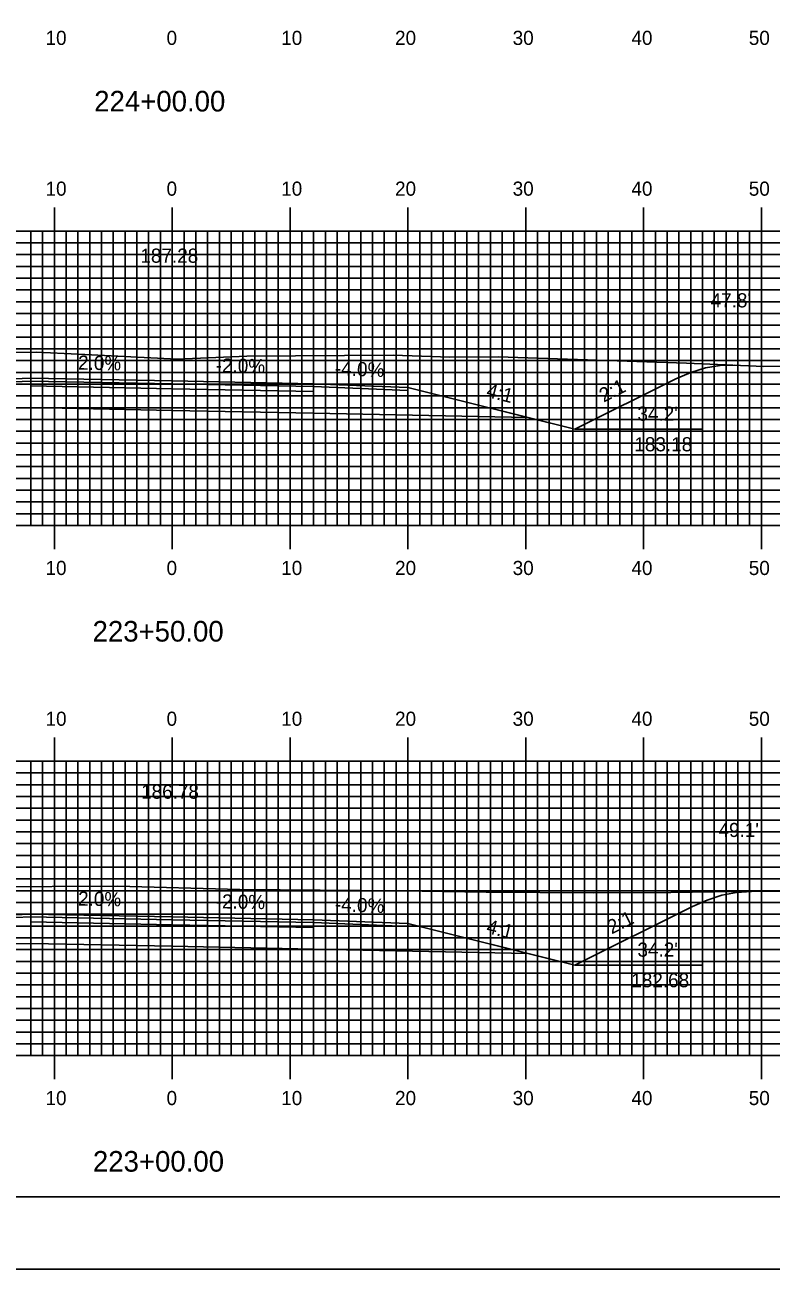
# Model space of a CAD drawing. Extents: x 1797994 to 1798337, y 442591 to 442811.
# Drawn here: x 1798147.5 to 1798210.8, y 442590.5 to 442696.2 of the extents above; entities that cross this region are included whole.
import ezdxf

# ---------------------------------------------------------------- set-up
doc = ezdxf.new("R2010")
doc.units = 0
for name, color, linetype in [('ANNOTATION', 7, 'Continuous'), ('BORDER', 7, 'Continuous'), ('D_Roadway_Centerline', 7, 'Continuous'), ('D_Roadway_Centerline_Text', 7, 'Continuous'), ('D_Roadway_Edge_Shoulder', 7, 'Continuous'), ('D_Roadway_Edge_TW', 7, 'Continuous'), ('D_Roadway_Pavement', 7, 'Continuous'), ('D_Roadway_SlopeLines', 7, 'Continuous'), ('D_Roadway_SubGrade', 7, 'Continuous'), ('D_Text_Standard', 7, 'Continuous'), ('H_V ANNOTATION', 7, 'Continuous'), ('MAJOR', 7, 'Continuous'), ('MINOR', 7, 'Continuous'), ('PDRAIN', 7, 'Continuous'), ('PLOT BOUNDARY', 7, 'Continuous'), ('S_Roadway_Centerline', 7, 'Continuous')]:
    doc.layers.add(name, color=color, linetype=linetype)

msp = doc.modelspace()

# ---------------------------------------------------------------- linework, layer by layer
at = {"layer": 'BORDER'}
msp.add_lwpolyline([(1798010.36, 442596.67), (1798330.36, 442596.67), (1798330.36, 442806.67), (1798010.36, 442806.67)], close=True, dxfattribs=at)
at = {"layer": 'D_Roadway_Centerline'}
for points in [[(1798111.32, 442668.33), (1798112.57, 442668.24), (1798113.82, 442668), (1798115.07, 442667.61), (1798116.32, 442667.06), (1798125.78, 442662.33), (1798129.78, 442663.33), (1798139.96, 442665.87), (1798147.96, 442666.19), (1798159.96, 442665.95), (1798171.96, 442665.71), (1798179.96, 442665.39), (1798190.13, 442662.85), (1798194.13, 442661.85), (1798202.71, 442666.13), (1798203.96, 442666.67), (1798205.21, 442667.05), (1798206.46, 442667.25), (1798207.71, 442667.28)], [(1798109.84, 442623.56), (1798111.09, 442623.48), (1798112.34, 442623.24), (1798113.59, 442622.85), (1798114.84, 442622.3), (1798125.78, 442616.83), (1798129.78, 442617.83), (1798139.96, 442620.37), (1798147.96, 442620.69), (1798159.96, 442620.45), (1798171.96, 442620.21), (1798179.96, 442619.89), (1798190.13, 442617.35), (1798194.13, 442616.35), (1798204.11, 442621.33), (1798205.36, 442621.88), (1798206.61, 442622.28), (1798207.86, 442622.52), (1798209.11, 442622.61)]]:
    msp.add_lwpolyline(points, dxfattribs=at)
at = {"layer": 'D_Roadway_Edge_Shoulder'}
for points in [[(1798147.96, 442666.19), (1798139.96, 442665.87), (1798139.96, 442665.62), (1798147.96, 442665.94)], [(1798171.96, 442665.71), (1798179.96, 442665.39), (1798179.96, 442665.14), (1798171.96, 442665.46)], [(1798147.96, 442620.69), (1798139.96, 442620.37), (1798139.96, 442620.12), (1798147.96, 442620.44)], [(1798171.96, 442620.21), (1798179.96, 442619.89), (1798179.96, 442619.64), (1798171.96, 442619.96)]]:
    msp.add_lwpolyline(points, close=True, dxfattribs=at)
at = {"layer": 'D_Roadway_Edge_TW'}
for points in [[(1798147.96, 442665.94), (1798147.96, 442666.19), (1798159.96, 442665.95), (1798171.96, 442665.71), (1798171.96, 442665.46), (1798159.96, 442665.7)], [(1798147.96, 442620.44), (1798147.96, 442620.69), (1798159.96, 442620.45), (1798171.96, 442620.21), (1798171.96, 442619.96), (1798159.96, 442620.2)]]:
    msp.add_lwpolyline(points, close=True, dxfattribs=at)
at = {"layer": 'D_Roadway_Pavement'}
for points in [[(1798147.96, 442665.52), (1798147.96, 442665.94), (1798159.96, 442665.7), (1798171.96, 442665.46), (1798171.96, 442665.04), (1798159.96, 442665.28)], [(1798147.96, 442620.02), (1798147.96, 442620.44), (1798159.96, 442620.2), (1798171.96, 442619.96), (1798171.96, 442619.54), (1798159.96, 442619.78)]]:
    msp.add_lwpolyline(points, close=True, dxfattribs=at)
at = {"layer": 'D_Roadway_SlopeLines'}
for points in [[(1798194.13, 442661.85), (1798202.71, 442666.13), (1798203.96, 442666.67), (1798205.21, 442667.05), (1798206.46, 442667.25), (1798207.71, 442667.28)], [(1798179.96, 442665.39), (1798194.13, 442661.85)], [(1798194.13, 442616.35), (1798204.11, 442621.33), (1798205.36, 442621.88), (1798206.61, 442622.28), (1798207.86, 442622.52), (1798209.11, 442622.61)], [(1798179.96, 442619.89), (1798194.13, 442616.35)]]:
    msp.add_lwpolyline(points, dxfattribs=at)
at = {"layer": 'D_Roadway_SubGrade'}
for points in [[(1798147.96, 442663.69), (1798129.78, 442663.33), (1798139.96, 442665.87), (1798139.96, 442665.62), (1798147.96, 442665.94), (1798159.96, 442665.7), (1798171.96, 442665.46), (1798179.96, 442665.14), (1798179.96, 442665.39), (1798190.13, 442662.85), (1798171.96, 442663.21), (1798159.96, 442663.45)], [(1798147.96, 442618.19), (1798129.78, 442617.83), (1798139.96, 442620.37), (1798139.96, 442620.12), (1798147.96, 442620.44), (1798159.96, 442620.2), (1798171.96, 442619.96), (1798179.96, 442619.64), (1798179.96, 442619.89), (1798190.13, 442617.35), (1798171.96, 442617.71), (1798159.96, 442617.95)]]:
    msp.add_lwpolyline(points, close=True, dxfattribs=at)
at = {"layer": 'MAJOR'}
for p, q in [((1798149.96, 442680.67), (1798149.96, 442678.67)), ((1798159.96, 442680.67), (1798159.96, 442678.67)), ((1798169.96, 442680.67), (1798169.96, 442678.67)), ((1798179.96, 442680.67), (1798179.96, 442678.67)), ((1798189.96, 442680.67), (1798189.96, 442678.67)), ((1798199.96, 442680.67), (1798199.96, 442678.67)), ((1798209.96, 442680.67), (1798209.96, 442678.67)), ((1798019.96, 442678.67), (1798299.96, 442678.67)), ((1798019.96, 442678.67), (1798299.96, 442678.67)), ((1798149.96, 442653.67), (1798149.96, 442678.67)), ((1798159.96, 442653.67), (1798159.96, 442678.67)), ((1798169.96, 442653.67), (1798169.96, 442678.67)), ((1798179.96, 442653.67), (1798179.96, 442678.67)), ((1798189.96, 442653.67), (1798189.96, 442678.67)), ((1798199.96, 442653.67), (1798199.96, 442678.67)), ((1798209.96, 442653.67), (1798209.96, 442678.67)), ((1798019.96, 442673.67), (1798299.96, 442673.67)), ((1798019.96, 442668.67), (1798299.96, 442668.67)), ((1798019.96, 442663.67), (1798299.96, 442663.67)), ((1798019.96, 442658.67), (1798299.96, 442658.67)), ((1798019.96, 442653.67), (1798299.96, 442653.67)), ((1798019.96, 442653.67), (1798299.96, 442653.67)), ((1798149.96, 442651.66), (1798149.96, 442653.67)), ((1798159.96, 442651.66), (1798159.96, 442653.67)), ((1798169.96, 442651.66), (1798169.96, 442653.67)), ((1798179.96, 442651.66), (1798179.96, 442653.67)), ((1798189.96, 442651.66), (1798189.96, 442653.67)), ((1798199.96, 442651.66), (1798199.96, 442653.67)), ((1798209.96, 442651.66), (1798209.96, 442653.67)), ((1798149.96, 442635.67), (1798149.96, 442633.67)), ((1798159.96, 442635.67), (1798159.96, 442633.67)), ((1798169.96, 442635.67), (1798169.96, 442633.67)), ((1798179.96, 442635.67), (1798179.96, 442633.67)), ((1798189.96, 442635.67), (1798189.96, 442633.67)), ((1798199.96, 442635.67), (1798199.96, 442633.67)), ((1798209.96, 442635.67), (1798209.96, 442633.67)), ((1798019.96, 442633.67), (1798299.96, 442633.67)), ((1798019.96, 442633.67), (1798299.96, 442633.67)), ((1798149.96, 442608.67), (1798149.96, 442633.67)), ((1798159.96, 442608.67), (1798159.96, 442633.67)), ((1798169.96, 442608.67), (1798169.96, 442633.67)), ((1798179.96, 442608.67), (1798179.96, 442633.67)), ((1798189.96, 442608.67), (1798189.96, 442633.67)), ((1798199.96, 442608.67), (1798199.96, 442633.67)), ((1798209.96, 442608.67), (1798209.96, 442633.67)), ((1798019.96, 442628.67), (1798299.96, 442628.67)), ((1798019.96, 442623.67), (1798299.96, 442623.67)), ((1798019.96, 442618.67), (1798299.96, 442618.67)), ((1798019.96, 442613.67), (1798299.96, 442613.67)), ((1798019.96, 442608.67), (1798299.96, 442608.67)), ((1798019.96, 442608.67), (1798299.96, 442608.67)), ((1798149.96, 442606.66), (1798149.96, 442608.67)), ((1798159.96, 442606.66), (1798159.96, 442608.67)), ((1798169.96, 442606.66), (1798169.96, 442608.67)), ((1798179.96, 442606.66), (1798179.96, 442608.67)), ((1798189.96, 442606.66), (1798189.96, 442608.67)), ((1798199.96, 442606.66), (1798199.96, 442608.67)), ((1798209.96, 442606.66), (1798209.96, 442608.67))]:
    msp.add_line(p, q, dxfattribs=at)
at = {"layer": 'MINOR'}
for p, q in [((1798147.96, 442653.67), (1798147.96, 442678.67)), ((1798148.96, 442653.67), (1798148.96, 442678.67)), ((1798150.96, 442653.67), (1798150.96, 442678.67)), ((1798151.96, 442653.67), (1798151.96, 442678.67)), ((1798152.96, 442653.67), (1798152.96, 442678.67)), ((1798153.96, 442653.67), (1798153.96, 442678.67)), ((1798154.96, 442653.67), (1798154.96, 442678.67)), ((1798155.96, 442653.67), (1798155.96, 442678.67)), ((1798156.96, 442653.67), (1798156.96, 442678.67)), ((1798157.96, 442653.67), (1798157.96, 442678.67)), ((1798158.96, 442653.67), (1798158.96, 442678.67)), ((1798160.96, 442653.67), (1798160.96, 442678.67)), ((1798161.96, 442653.67), (1798161.96, 442678.67)), ((1798162.96, 442653.67), (1798162.96, 442678.67)), ((1798163.96, 442653.67), (1798163.96, 442678.67)), ((1798164.96, 442653.67), (1798164.96, 442678.67)), ((1798165.96, 442653.67), (1798165.96, 442678.67)), ((1798166.96, 442653.67), (1798166.96, 442678.67)), ((1798167.96, 442653.67), (1798167.96, 442678.67)), ((1798168.96, 442653.67), (1798168.96, 442678.67)), ((1798170.96, 442653.67), (1798170.96, 442678.67)), ((1798171.96, 442653.67), (1798171.96, 442678.67)), ((1798172.96, 442653.67), (1798172.96, 442678.67)), ((1798173.96, 442653.67), (1798173.96, 442678.67)), ((1798174.96, 442653.67), (1798174.96, 442678.67)), ((1798175.96, 442653.67), (1798175.96, 442678.67)), ((1798176.96, 442653.67), (1798176.96, 442678.67)), ((1798177.96, 442653.67), (1798177.96, 442678.67)), ((1798178.96, 442653.67), (1798178.96, 442678.67)), ((1798180.96, 442653.67), (1798180.96, 442678.67)), ((1798181.96, 442653.67), (1798181.96, 442678.67)), ((1798182.96, 442653.67), (1798182.96, 442678.67)), ((1798183.96, 442653.67), (1798183.96, 442678.67)), ((1798184.96, 442653.67), (1798184.96, 442678.67)), ((1798185.96, 442653.67), (1798185.96, 442678.67)), ((1798186.96, 442653.67), (1798186.96, 442678.67)), ((1798187.96, 442653.67), (1798187.96, 442678.67)), ((1798188.96, 442653.67), (1798188.96, 442678.67)), ((1798190.96, 442653.67), (1798190.96, 442678.67)), ((1798191.96, 442653.67), (1798191.96, 442678.67)), ((1798192.96, 442653.67), (1798192.96, 442678.67)), ((1798193.96, 442653.67), (1798193.96, 442678.67)), ((1798194.96, 442653.67), (1798194.96, 442678.67)), ((1798195.96, 442653.67), (1798195.96, 442678.67)), ((1798196.96, 442653.67), (1798196.96, 442678.67)), ((1798197.96, 442653.67), (1798197.96, 442678.67)), ((1798198.96, 442653.67), (1798198.96, 442678.67)), ((1798200.96, 442653.67), (1798200.96, 442678.67)), ((1798201.96, 442653.67), (1798201.96, 442678.67)), ((1798202.96, 442653.67), (1798202.96, 442678.67)), ((1798203.96, 442653.67), (1798203.96, 442678.67)), ((1798204.96, 442653.67), (1798204.96, 442678.67)), ((1798205.96, 442653.67), (1798205.96, 442678.67)), ((1798206.96, 442653.67), (1798206.96, 442678.67)), ((1798207.96, 442653.67), (1798207.96, 442678.67)), ((1798208.96, 442653.67), (1798208.96, 442678.67)), ((1798019.96, 442677.67), (1798299.96, 442677.67)), ((1798019.96, 442676.67), (1798299.96, 442676.67)), ((1798019.96, 442675.67), (1798299.96, 442675.67)), ((1798019.96, 442674.67), (1798299.96, 442674.67)), ((1798019.96, 442672.67), (1798299.96, 442672.67)), ((1798019.96, 442671.67), (1798299.96, 442671.67)), ((1798019.96, 442670.67), (1798299.96, 442670.67)), ((1798019.96, 442669.67), (1798299.96, 442669.67)), ((1798019.96, 442667.67), (1798299.96, 442667.67)), ((1798019.96, 442666.67), (1798299.96, 442666.67)), ((1798019.96, 442665.67), (1798299.96, 442665.67)), ((1798019.96, 442664.67), (1798299.96, 442664.67)), ((1798019.96, 442662.67), (1798299.96, 442662.67)), ((1798019.96, 442661.67), (1798299.96, 442661.67)), ((1798019.96, 442660.67), (1798299.96, 442660.67)), ((1798019.96, 442659.67), (1798299.96, 442659.67)), ((1798019.96, 442657.67), (1798299.96, 442657.67)), ((1798019.96, 442656.67), (1798299.96, 442656.67)), ((1798019.96, 442655.67), (1798299.96, 442655.67)), ((1798019.96, 442654.67), (1798299.96, 442654.67)), ((1798147.96, 442608.67), (1798147.96, 442633.67)), ((1798148.96, 442608.67), (1798148.96, 442633.67)), ((1798150.96, 442608.67), (1798150.96, 442633.67)), ((1798151.96, 442608.67), (1798151.96, 442633.67)), ((1798152.96, 442608.67), (1798152.96, 442633.67)), ((1798153.96, 442608.67), (1798153.96, 442633.67)), ((1798154.96, 442608.67), (1798154.96, 442633.67)), ((1798155.96, 442608.67), (1798155.96, 442633.67)), ((1798156.96, 442608.67), (1798156.96, 442633.67)), ((1798157.96, 442608.67), (1798157.96, 442633.67)), ((1798158.96, 442608.67), (1798158.96, 442633.67)), ((1798160.96, 442608.67), (1798160.96, 442633.67)), ((1798161.96, 442608.67), (1798161.96, 442633.67)), ((1798162.96, 442608.67), (1798162.96, 442633.67)), ((1798163.96, 442608.67), (1798163.96, 442633.67)), ((1798164.96, 442608.67), (1798164.96, 442633.67)), ((1798165.96, 442608.67), (1798165.96, 442633.67)), ((1798166.96, 442608.67), (1798166.96, 442633.67)), ((1798167.96, 442608.67), (1798167.96, 442633.67)), ((1798168.96, 442608.67), (1798168.96, 442633.67)), ((1798170.96, 442608.67), (1798170.96, 442633.67)), ((1798171.96, 442608.67), (1798171.96, 442633.67)), ((1798172.96, 442608.67), (1798172.96, 442633.67)), ((1798173.96, 442608.67), (1798173.96, 442633.67)), ((1798174.96, 442608.67), (1798174.96, 442633.67)), ((1798175.96, 442608.67), (1798175.96, 442633.67)), ((1798176.96, 442608.67), (1798176.96, 442633.67)), ((1798177.96, 442608.67), (1798177.96, 442633.67)), ((1798178.96, 442608.67), (1798178.96, 442633.67)), ((1798180.96, 442608.67), (1798180.96, 442633.67)), ((1798181.96, 442608.67), (1798181.96, 442633.67)), ((1798182.96, 442608.67), (1798182.96, 442633.67)), ((1798183.96, 442608.67), (1798183.96, 442633.67)), ((1798184.96, 442608.67), (1798184.96, 442633.67)), ((1798185.96, 442608.67), (1798185.96, 442633.67)), ((1798186.96, 442608.67), (1798186.96, 442633.67)), ((1798187.96, 442608.67), (1798187.96, 442633.67)), ((1798188.96, 442608.67), (1798188.96, 442633.67)), ((1798190.96, 442608.67), (1798190.96, 442633.67)), ((1798191.96, 442608.67), (1798191.96, 442633.67)), ((1798192.96, 442608.67), (1798192.96, 442633.67)), ((1798193.96, 442608.67), (1798193.96, 442633.67)), ((1798194.96, 442608.67), (1798194.96, 442633.67)), ((1798195.96, 442608.67), (1798195.96, 442633.67)), ((1798196.96, 442608.67), (1798196.96, 442633.67)), ((1798197.96, 442608.67), (1798197.96, 442633.67)), ((1798198.96, 442608.67), (1798198.96, 442633.67)), ((1798200.96, 442608.67), (1798200.96, 442633.67)), ((1798201.96, 442608.67), (1798201.96, 442633.67)), ((1798202.96, 442608.67), (1798202.96, 442633.67)), ((1798203.96, 442608.67), (1798203.96, 442633.67)), ((1798204.96, 442608.67), (1798204.96, 442633.67)), ((1798205.96, 442608.67), (1798205.96, 442633.67)), ((1798206.96, 442608.67), (1798206.96, 442633.67)), ((1798207.96, 442608.67), (1798207.96, 442633.67)), ((1798208.96, 442608.67), (1798208.96, 442633.67)), ((1798019.96, 442632.67), (1798299.96, 442632.67)), ((1798019.96, 442631.67), (1798299.96, 442631.67)), ((1798019.96, 442630.67), (1798299.96, 442630.67)), ((1798019.96, 442629.67), (1798299.96, 442629.67)), ((1798019.96, 442627.67), (1798299.96, 442627.67)), ((1798019.96, 442626.67), (1798299.96, 442626.67)), ((1798019.96, 442625.67), (1798299.96, 442625.67)), ((1798019.96, 442624.67), (1798299.96, 442624.67)), ((1798019.96, 442622.67), (1798299.96, 442622.67)), ((1798019.96, 442621.67), (1798299.96, 442621.67)), ((1798019.96, 442620.67), (1798299.96, 442620.67)), ((1798019.96, 442619.67), (1798299.96, 442619.67)), ((1798019.96, 442617.67), (1798299.96, 442617.67)), ((1798019.96, 442616.67), (1798299.96, 442616.67)), ((1798019.96, 442615.67), (1798299.96, 442615.67)), ((1798019.96, 442614.67), (1798299.96, 442614.67)), ((1798019.96, 442612.67), (1798299.96, 442612.67)), ((1798019.96, 442611.67), (1798299.96, 442611.67)), ((1798019.96, 442610.67), (1798299.96, 442610.67)), ((1798019.96, 442609.67), (1798299.96, 442609.67))]:
    msp.add_line(p, q, dxfattribs=at)
at = {"layer": 'PDRAIN'}
for p, q in [((1798194.13, 442661.85), (1798204.9, 442661.85)), ((1798194.13, 442616.35), (1798204.9, 442616.35))]:
    msp.add_line(p, q, dxfattribs=at)
at = {"layer": 'PLOT BOUNDARY'}
msp.add_lwpolyline([(1797994.17, 442590.55), (1798334.17, 442590.55), (1798334.17, 442810.55), (1797994.17, 442810.55)], close=True, dxfattribs=at)
at = {"layer": 'S_Roadway_Centerline'}
for points in [[(1798102.25, 442668.41), (1798102.51, 442668.41), (1798105.32, 442668.38), (1798123.11, 442668.23), (1798124.43, 442668.16), (1798126.54, 442668.15), (1798137.46, 442668.24), (1798145.98, 442668.37), (1798148.44, 442668.4), (1798151.99, 442668.21), (1798160.37, 442667.79), (1798166.3, 442668.04), (1798178.7, 442668.14), (1798183.51, 442667.97), (1798187.61, 442668), (1798203.6, 442667.45), (1798210.16, 442667.18), (1798218.97, 442667.3)], [(1798019.96, 442624.18), (1798026.96, 442624.23), (1798036.73, 442624.33), (1798039.99, 442624.27), (1798059.51, 442623.72), (1798061.88, 442623.71), (1798065.3, 442623.74), (1798080.87, 442623.7), (1798092, 442623.71), (1798102.39, 442623.6), (1798118.19, 442623.52), (1798120.17, 442623.54), (1798121.59, 442623.48), (1798143.17, 442622.99), (1798143.68, 442622.99), (1798144.17, 442623), (1798155.33, 442623.07), (1798165.69, 442622.78), (1798179.35, 442622.67), (1798186.61, 442622.56), (1798195.7, 442622.49), (1798202.28, 442622.51), (1798207.69, 442622.6), (1798213.43, 442622.63)]]:
    msp.add_lwpolyline(points, dxfattribs=at)

# ---------------------------------------------------------------- texts
at = {"layer": 'ANNOTATION'}
for s, rotation, p in [('2.0%', 358.8542, (1798151.96, 442666.91)), ('-2.0%', 358.8542, (1798163.64, 442666.68)), ('-4.0%', 357.7094, (1798173.75, 442666.44)), ('2:1', 26.5651, (1798196.57, 442664.1)), ('4:1', 345.9638, (1798186.55, 442664.6)), ('2.0%', 358.8542, (1798151.96, 442621.41)), ('-2.0%', 358.8542, (1798163.64, 442621.18)), ('-4.0%', 357.7094, (1798173.75, 442620.94)), ('2:1', 26.5651, (1798197.26, 442618.95)), ('4:1', 345.9638, (1798186.55, 442619.1))]:
    msp.add_text(s, height=1.2, rotation=rotation, dxfattribs=at).set_placement(p)
for s, p in [("34.2'", (1798199.44, 442662.57)), ('183.18', (1798199.18, 442659.97)), ("34.2'", (1798199.44, 442617.07)), ('182.68', (1798198.92, 442614.47))]:
    msp.add_text(s, height=1.2, dxfattribs=at).set_placement(p)
at = {"layer": 'D_Roadway_Centerline'}
for s, p in [('C', (1798159.95, 442665.95)), ('L', (1798159.96, 442665.94)), ('C', (1798159.95, 442620.45)), ('L', (1798159.96, 442620.44))]:
    msp.add_text(s, height=0.0146, dxfattribs=at).set_placement(p)
at = {"layer": 'D_Roadway_Centerline_Text'}
for s, p in [('187.28', (1798157.26, 442675.98)), ('186.78', (1798157.32, 442630.48))]:
    msp.add_text(s, height=1.2, dxfattribs=at).set_placement(p)
at = {"layer": 'D_Text_Standard'}
for s, p in [("47.8'", (1798205.65, 442672.19)), ("49.1'", (1798206.32, 442627.23))]:
    msp.add_text(s, height=1.2, dxfattribs=at).set_placement(p)
at = {"layer": 'H_V ANNOTATION'}
for s, height, p in [('10', 1.2, (1798149.21, 442694.47)), ('0', 1.2, (1798159.48, 442694.47)), ('10', 1.2, (1798169.21, 442694.47)), ('20', 1.2, (1798178.87, 442694.47)), ('30', 1.2, (1798188.85, 442694.47)), ('40', 1.2, (1798198.93, 442694.47)), ('50', 1.2, (1798208.89, 442694.47)), ('224+00.00', 1.75, (1798153.34, 442688.82)), ('10', 1.2, (1798149.21, 442681.67)), ('0', 1.2, (1798159.48, 442681.67)), ('10', 1.2, (1798169.21, 442681.67)), ('20', 1.2, (1798178.87, 442681.67)), ('30', 1.2, (1798188.85, 442681.67)), ('40', 1.2, (1798198.93, 442681.67)), ('50', 1.2, (1798208.89, 442681.67)), ('10', 1.2, (1798149.21, 442649.47)), ('0', 1.2, (1798159.48, 442649.47)), ('10', 1.2, (1798169.21, 442649.47)), ('20', 1.2, (1798178.87, 442649.47)), ('30', 1.2, (1798188.85, 442649.47)), ('40', 1.2, (1798198.93, 442649.47)), ('50', 1.2, (1798208.89, 442649.47)), ('223+50.00', 1.75, (1798153.2, 442643.82)), ('10', 1.2, (1798149.21, 442636.67)), ('0', 1.2, (1798159.48, 442636.67)), ('10', 1.2, (1798169.21, 442636.67)), ('20', 1.2, (1798178.87, 442636.67)), ('30', 1.2, (1798188.85, 442636.67)), ('40', 1.2, (1798198.93, 442636.67)), ('50', 1.2, (1798208.89, 442636.67)), ('10', 1.2, (1798149.21, 442604.47)), ('0', 1.2, (1798159.48, 442604.47)), ('10', 1.2, (1798169.21, 442604.47)), ('20', 1.2, (1798178.87, 442604.47)), ('30', 1.2, (1798188.85, 442604.47)), ('40', 1.2, (1798198.93, 442604.47)), ('50', 1.2, (1798208.89, 442604.47)), ('223+00.00', 1.75, (1798153.23, 442598.82))]:
    msp.add_text(s, height=height, dxfattribs=at).set_placement(p)

doc.saveas('drawing.dxf')
